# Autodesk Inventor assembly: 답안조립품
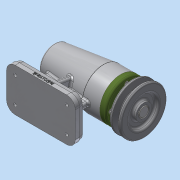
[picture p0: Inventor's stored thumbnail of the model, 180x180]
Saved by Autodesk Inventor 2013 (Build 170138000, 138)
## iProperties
Created: 2017-01
Part Number: 답안조립품
Document SubType Name: Assembly
Designer: dgall
Author: dgall
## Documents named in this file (12)
- C:\Users\dgall\Desktop\470107V1006\답안조립품.iam
- C:\Users\dgall\Desktop\470107V1006\답안본체.ipt
- C:\Users\dgall\Desktop\470107V1006\V벨트풀리.ipt
- C:\Users\dgall\Desktop\470107V1006\멈춤나사 M3x8.ipt
- C:\Users\dgall\Desktop\470107V1006\베어링 6004.ipt
- C:\Users\dgall\Desktop\470107V1006\베어링 51202.ipt
- C:\Users\dgall\Desktop\470107V1006\볼트 M4 x 12.ipt
- C:\Users\dgall\Desktop\470107V1006\어댑터슬리브.ipt
- C:\Users\dgall\Desktop\470107V1006\오일 실.ipt
- C:\Users\dgall\Desktop\470107V1006\축.ipt
- C:\Users\dgall\Desktop\470107V1006\커버.ipt
- C:\Users\dgall\Desktop\470107V1006\키 5 x 5 x 16.ipt
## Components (6 placed, 2 different names)
1. V벨트풀리:1
2. ISO 4762 M4 x 12:1
3. ISO 4762 M4 x 12:2
4. ISO 4762 M4 x 12:3
5. ISO 4762 M4 x 12:4
6. ISO 4762 M4 x 12:5
